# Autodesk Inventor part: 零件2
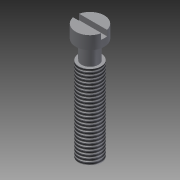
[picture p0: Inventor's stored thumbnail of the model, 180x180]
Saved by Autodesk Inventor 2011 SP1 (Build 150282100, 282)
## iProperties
Created: 2014-02
Part Number: 零件2
Document SubType Name: Modeling
Designer: yn
Density: 1 g/cm^3
Author: yn
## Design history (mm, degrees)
sketch "草图1"
  geometry: C1 r 6 at (0, 0); 1 further point
  constraints: 1 centre point, 1 coincident
  dimensions: "d0" = 12 diameter of C1
extrude "拉伸1" new body sketch "草图1" distance "d1" = 45; taper "d2" = 0 deg
sketch "草图2"
  geometry: C1 r 6 at (0, 0) reference; C2 r 4.522 at (0, 0)
  constraints: 1 centre point, 1 coincident
extrude "拉伸2" join sketch "草图2" distance "d3" = 10; taper "d4" = 0 deg
sketch "草图3"
  geometry: C1 r 7.7 at (0, 0); 1 further point
  constraints: 1 centre point, 1 coincident
extrude "拉伸3" join sketch "草图3" distance "d5" = 7; taper "d6" = 0 deg
sketch "草图4"
  geometry: L1 (-7.522, -1.649)-(7.522, -1.649); L2 (7.522, 1.649)-(-7.522, 1.649); A1 r 7.7 centre (0, 0) between (-7.522, 1.649) and (-7.522, -1.649) reference; 1 further point
  constraints: 4 end point, 4 point on circle, 1 horizontal, 1 parallel, 1 vertical alignment
extrude "拉伸4" cut sketch "草图4" distance "d8" = 3; taper "d9" = 0 deg
fillet "圆角1" dims "d10" = 2
feature "螺纹1" dims "d11" = 10, "d12" = 0
node "实体1"
